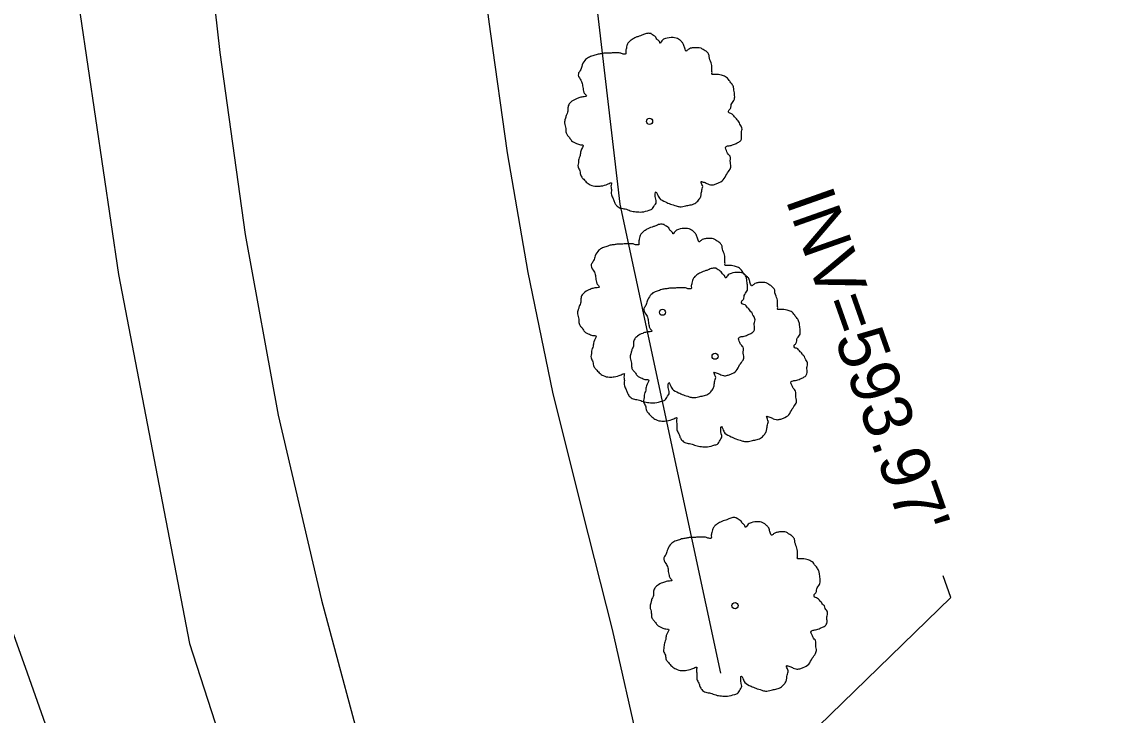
# Model space of a CAD drawing. Extents: x 2004847 to 2009016, y 1134161 to 1140101.
# Drawn here: x 2005249.9 to 2005339.3, y 1139472.4 to 1139529 of the extents above; entities that cross this region are included whole.
import ezdxf

# ---------------------------------------------------------------- set-up
doc = ezdxf.new("R2010")
doc.units = 0
for name, color, linetype in [('RD_EX_DR_Inlet_txCode', 7, 'Continuous'), ('RD_EX_Fence_Other', 7, 'Continuous'), ('RD_EX_H2O', 7, 'Continuous'), ('RD_EX_Road', 7, 'Continuous'), ('RD_EX_VEG', 7, 'Continuous')]:
    doc.layers.add(name, color=color, linetype=linetype)

msp = doc.modelspace()

# ---------------------------------------------------------------- linework, layer by layer
at = {"layer": 'RD_EX_DR_Inlet_txCode'}
msp.add_lwpolyline([(2005310.045, 1139466.714), (2005325.794, 1139482.013), (2005325.165, 1139483.793)], dxfattribs=at)
at = {"layer": 'RD_EX_Fence_Other'}
msp.add_lwpolyline([(2005253.027, 1139716.132), (2005238.254, 1139668.781), (2005212.869, 1139585.207), (2005223.769, 1139551.444), (2005241.149, 1139501.523), (2005250.303, 1139475.866), (2005274.937, 1139406.133)], dxfattribs=at)
at = {"layer": 'RD_EX_H2O'}
msp.add_line((2005298.755, 1139514.148), (2005306.974, 1139475.853), dxfattribs=at)
for points in [[(2005258.132, 1139714.456), (2005253.872, 1139663.93), (2005250.076, 1139582.798), (2005251.507, 1139550.898), (2005257.79, 1139508.395), (2005263.585, 1139478.258), (2005286.366, 1139407.794), (2005304.78, 1139341.828)], [(2005299.739, 1139659.564), (2005292.279, 1139582.182), (2005293.644, 1139557.733), (2005298.755, 1139514.148)]]:
    msp.add_lwpolyline(points, dxfattribs=at)
at = {"layer": 'RD_EX_Road'}
for points in [[(2005262.051, 1139571.916), (2005263.041, 1139556.953), (2005264.31, 1139542.01), (2005266.061, 1139526.537), (2005268.134, 1139511.675), (2005270.817, 1139496.924), (2005274.378, 1139481.81), (2005278.256, 1139467.332), (2005282.356, 1139452.916), (2005286.707, 1139438.571), (2005291.182, 1139424.261), (2005295.677, 1139409.956), (2005300.517, 1139395.441), (2005305.551, 1139381.315), (2005310.576, 1139367.186), (2005315.506, 1139353.023), (2005320.719, 1139338.96), (2005325.801, 1139324.851), (2005330.861, 1139310.729), (2005335.767, 1139296.554), (2005340.823, 1139282.434)], [(2005284.086, 1139567.589), (2005284.726, 1139557.612), (2005285.696, 1139548.131), (2005286.816, 1139538.175), (2005288.153, 1139528.259), (2005289.539, 1139518.351), (2005291.221, 1139508.575), (2005293.244, 1139498.788), (2005295.658, 1139489.087), (2005298.121, 1139479.396), (2005300.33, 1139469.65), (2005303.203, 1139460.049), (2005305.845, 1139450.53), (2005309.03, 1139441.031), (2005312.07, 1139431.495), (2005314.223, 1139425.334), (2005316.148, 1139423.068), (2005322.431, 1139419.852), (2005326.067, 1139418.258), (2005330.045, 1139416.594), (2005332.094, 1139409.223)]]:
    msp.add_lwpolyline(points, dxfattribs=at)
at = {"layer": 'RD_EX_VEG'}
for centre, radius in [((2005301.168, 1139520.915), 0.25), ((2005301.155, 1139520.896), 0.0001), ((2005302.228, 1139505.324), 0.25), ((2005302.215, 1139505.305), 0.0001), ((2005306.525, 1139501.731), 0.25), ((2005306.512, 1139501.713), 0.0001), ((2005308.155, 1139481.359), 0.25), ((2005308.142, 1139481.34), 0.0001)]:
    msp.add_circle(centre, radius, dxfattribs=at)
for points in [[(2005301.299, 1139528.082), (2005301, 1139528.107), (2005300.675, 1139528.007), (2005300.425, 1139527.907), (2005300.2, 1139527.832), (2005299.975, 1139527.732), (2005299.675, 1139527.557), (2005299.45, 1139527.357), (2005299.325, 1139527.108), (2005299.275, 1139526.883), (2005299.225, 1139526.608), (2005299.225, 1139526.433), (2005299.1, 1139526.408), (2005298.95, 1139526.433), (2005298.701, 1139526.508), (2005298.451, 1139526.508), (2005298.201, 1139526.508), (2005297.851, 1139526.483), (2005297.501, 1139526.483), (2005297.226, 1139526.433), (2005296.901, 1139526.383), (2005296.526, 1139526.258), (2005296.177, 1139526.133), (2005295.877, 1139525.883), (2005295.627, 1139525.408), (2005295.502, 1139525.058), (2005295.352, 1139524.809), (2005295.502, 1139524.359), (2005295.677, 1139524.009), (2005295.702, 1139523.809), (2005295.777, 1139523.384), (2005295.877, 1139523.159), (2005296.002, 1139522.959), (2005295.927, 1139522.934), (2005295.552, 1139522.884), (2005295.252, 1139522.784), (2005294.827, 1139522.56), (2005294.602, 1139522.335), (2005294.502, 1139522.01), (2005294.477, 1139521.66), (2005294.377, 1139521.46), (2005294.302, 1139521.185), (2005294.277, 1139521.11), (2005294.227, 1139520.785), (2005294.327, 1139520.335), (2005294.352, 1139519.986), (2005294.477, 1139519.761), (2005294.627, 1139519.586), (2005294.802, 1139519.336), (2005295.202, 1139519.111), (2005295.527, 1139519.011), (2005295.727, 1139518.986), (2005295.552, 1139518.486), (2005295.502, 1139518.136), (2005295.377, 1139517.737), (2005295.377, 1139517.662), (2005295.327, 1139517.187), (2005295.477, 1139516.862), (2005295.552, 1139516.487), (2005295.727, 1139516.262), (2005296.002, 1139515.962), (2005296.327, 1139515.738), (2005296.826, 1139515.613), (2005297.226, 1139515.638), (2005297.801, 1139515.812), (2005298.051, 1139515.887), (2005298.026, 1139515.713), (2005298.051, 1139515.338), (2005298.051, 1139514.913), (2005298.201, 1139514.588), (2005298.301, 1139514.313), (2005298.451, 1139514.063), (2005298.776, 1139513.838), (2005299.175, 1139513.763), (2005299.6, 1139513.613), (2005300.05, 1139513.538), (2005300.55, 1139513.513), (2005301.149, 1139513.663), (2005301.424, 1139513.788), (2005301.524, 1139513.963), (2005301.724, 1139514.338), (2005301.674, 1139514.563), (2005301.699, 1139515.163), (2005301.799, 1139514.988), (2005301.974, 1139514.638), (2005302.474, 1139514.338), (2005302.874, 1139514.163), (2005303.348, 1139514.013), (2005303.648, 1139513.938), (2005304.123, 1139514.013), (2005304.498, 1139514.088), (2005304.873, 1139514.213), (2005305.173, 1139514.488), (2005305.348, 1139514.763), (2005305.398, 1139515.038), (2005305.473, 1139515.413), (2005305.523, 1139515.588)], [(2005305.523, 1139515.588), (2005305.448, 1139515.763), (2005305.398, 1139516.012), (2005305.473, 1139515.987), (2005305.647, 1139515.937), (2005305.922, 1139515.812), (2005306.147, 1139515.738), (2005306.472, 1139515.763), (2005306.747, 1139515.862), (2005307.197, 1139516.137), (2005307.472, 1139516.612), (2005307.747, 1139517.012), (2005307.822, 1139517.337), (2005307.772, 1139517.562), (2005307.747, 1139518.061), (2005307.547, 1139518.311), (2005307.497, 1139518.436), (2005307.397, 1139518.836), (2005307.472, 1139518.886), (2005307.747, 1139518.936), (2005308.121, 1139519.061), (2005308.396, 1139519.186), (2005308.621, 1139519.361), (2005308.696, 1139519.586), (2005308.671, 1139519.986), (2005308.721, 1139520.385), (2005308.646, 1139520.535), (2005308.546, 1139520.685), (2005308.471, 1139520.885), (2005308.321, 1139521.035), (2005308.221, 1139521.185), (2005308.121, 1139521.285), (2005307.996, 1139521.435), (2005307.822, 1139521.56), (2005307.672, 1139521.61), (2005307.622, 1139521.76), (2005307.772, 1139521.96), (2005307.822, 1139522.06), (2005307.846, 1139522.285), (2005308.071, 1139522.634), (2005308.121, 1139523.034), (2005308.071, 1139523.459), (2005308.021, 1139523.734), (2005307.871, 1139524.009), (2005307.672, 1139524.259), (2005307.547, 1139524.434), (2005307.372, 1139524.559), (2005307.047, 1139524.684), (2005306.797, 1139524.734), (2005306.447, 1139524.734), (2005306.247, 1139524.784), (2005306.272, 1139524.834), (2005306.272, 1139524.983), (2005306.272, 1139525.258), (2005306.197, 1139525.708), (2005306.047, 1139526.208), (2005306.047, 1139526.233), (2005305.947, 1139526.483), (2005305.722, 1139526.683), (2005305.548, 1139526.783), (2005305.348, 1139526.908), (2005305.098, 1139526.933), (2005304.798, 1139526.933), (2005304.523, 1139526.883), (2005304.323, 1139526.783), (2005304.148, 1139526.658), (2005304.073, 1139526.808), (2005303.973, 1139527.108), (2005303.923, 1139527.257), (2005303.773, 1139527.432), (2005303.548, 1139527.632), (2005303.099, 1139527.757), (2005302.474, 1139527.682), (2005302.174, 1139527.482), (2005302.024, 1139527.307), (2005301.974, 1139527.432), (2005301.774, 1139527.632), (2005301.674, 1139527.807), (2005301.499, 1139527.932), (2005301.349, 1139528.032), (2005301.249, 1139528.082)], [(2005302.36, 1139512.491), (2005302.06, 1139512.516), (2005301.735, 1139512.416), (2005301.485, 1139512.317), (2005301.26, 1139512.242), (2005301.035, 1139512.142), (2005300.735, 1139511.967), (2005300.51, 1139511.767), (2005300.385, 1139511.517), (2005300.335, 1139511.292), (2005300.285, 1139511.017), (2005300.285, 1139510.842), (2005300.161, 1139510.817), (2005300.011, 1139510.842), (2005299.761, 1139510.917), (2005299.511, 1139510.917), (2005299.261, 1139510.917), (2005298.911, 1139510.892), (2005298.561, 1139510.892), (2005298.286, 1139510.842), (2005297.961, 1139510.792), (2005297.587, 1139510.667), (2005297.237, 1139510.542), (2005296.937, 1139510.292), (2005296.687, 1139509.818), (2005296.562, 1139509.468), (2005296.412, 1139509.218), (2005296.562, 1139508.768), (2005296.737, 1139508.418), (2005296.762, 1139508.218), (2005296.837, 1139507.794), (2005296.937, 1139507.569), (2005297.062, 1139507.369), (2005296.987, 1139507.344), (2005296.612, 1139507.294), (2005296.312, 1139507.194), (2005295.887, 1139506.969), (2005295.662, 1139506.744), (2005295.562, 1139506.419), (2005295.538, 1139506.069), (2005295.438, 1139505.869), (2005295.363, 1139505.594), (2005295.338, 1139505.519), (2005295.288, 1139505.195), (2005295.388, 1139504.745), (2005295.413, 1139504.395), (2005295.538, 1139504.17), (2005295.687, 1139503.995), (2005295.862, 1139503.745), (2005296.262, 1139503.52), (2005296.587, 1139503.42), (2005296.787, 1139503.395), (2005296.612, 1139502.896), (2005296.562, 1139502.546), (2005296.437, 1139502.146), (2005296.437, 1139502.071), (2005296.387, 1139501.596), (2005296.537, 1139501.271), (2005296.612, 1139500.897), (2005296.787, 1139500.672), (2005297.062, 1139500.372), (2005297.387, 1139500.147), (2005297.887, 1139500.022), (2005298.286, 1139500.047), (2005298.861, 1139500.222), (2005299.111, 1139500.297), (2005299.086, 1139500.122), (2005299.111, 1139499.747), (2005299.111, 1139499.322), (2005299.261, 1139498.997), (2005299.361, 1139498.722), (2005299.511, 1139498.473), (2005299.836, 1139498.248), (2005300.235, 1139498.173), (2005300.66, 1139498.023), (2005301.11, 1139497.948), (2005301.61, 1139497.923), (2005302.21, 1139498.073), (2005302.484, 1139498.198), (2005302.584, 1139498.373), (2005302.784, 1139498.747), (2005302.734, 1139498.972), (2005302.759, 1139499.572), (2005302.859, 1139499.397), (2005303.034, 1139499.047), (2005303.534, 1139498.747), (2005303.934, 1139498.573), (2005304.409, 1139498.423), (2005304.709, 1139498.348), (2005305.183, 1139498.423), (2005305.558, 1139498.498), (2005305.933, 1139498.623), (2005306.233, 1139498.897), (2005306.408, 1139499.172), (2005306.458, 1139499.447), (2005306.533, 1139499.822), (2005306.583, 1139499.997)], [(2005306.583, 1139499.997), (2005306.508, 1139500.172), (2005306.458, 1139500.422), (2005306.533, 1139500.397), (2005306.708, 1139500.347), (2005306.983, 1139500.222), (2005307.207, 1139500.147), (2005307.532, 1139500.172), (2005307.807, 1139500.272), (2005308.257, 1139500.547), (2005308.532, 1139501.021), (2005308.807, 1139501.421), (2005308.882, 1139501.746), (2005308.832, 1139501.971), (2005308.807, 1139502.471), (2005308.607, 1139502.721), (2005308.557, 1139502.846), (2005308.457, 1139503.245), (2005308.532, 1139503.295), (2005308.807, 1139503.345), (2005309.182, 1139503.47), (2005309.456, 1139503.595), (2005309.681, 1139503.77), (2005309.756, 1139503.995), (2005309.731, 1139504.395), (2005309.781, 1139504.795), (2005309.706, 1139504.945), (2005309.606, 1139505.095), (2005309.531, 1139505.295), (2005309.381, 1139505.444), (2005309.282, 1139505.594), (2005309.182, 1139505.694), (2005309.057, 1139505.844), (2005308.882, 1139505.969), (2005308.732, 1139506.019), (2005308.682, 1139506.169), (2005308.832, 1139506.369), (2005308.882, 1139506.469), (2005308.907, 1139506.694), (2005309.132, 1139507.044), (2005309.182, 1139507.444), (2005309.132, 1139507.868), (2005309.082, 1139508.143), (2005308.932, 1139508.418), (2005308.732, 1139508.668), (2005308.607, 1139508.843), (2005308.432, 1139508.968), (2005308.107, 1139509.093), (2005307.857, 1139509.143), (2005307.507, 1139509.143), (2005307.307, 1139509.193), (2005307.332, 1139509.243), (2005307.332, 1139509.393), (2005307.332, 1139509.668), (2005307.257, 1139510.117), (2005307.107, 1139510.617), (2005307.107, 1139510.642), (2005307.007, 1139510.892), (2005306.783, 1139511.092), (2005306.608, 1139511.192), (2005306.408, 1139511.317), (2005306.158, 1139511.342), (2005305.858, 1139511.342), (2005305.583, 1139511.292), (2005305.383, 1139511.192), (2005305.208, 1139511.067), (2005305.133, 1139511.217), (2005305.033, 1139511.517), (2005304.983, 1139511.667), (2005304.833, 1139511.842), (2005304.609, 1139512.042), (2005304.159, 1139512.167), (2005303.534, 1139512.092), (2005303.234, 1139511.892), (2005303.084, 1139511.717), (2005303.034, 1139511.842), (2005302.834, 1139512.042), (2005302.734, 1139512.217), (2005302.559, 1139512.342), (2005302.41, 1139512.441), (2005302.31, 1139512.491)], [(2005306.657, 1139508.899), (2005306.357, 1139508.924), (2005306.032, 1139508.824), (2005305.782, 1139508.724), (2005305.557, 1139508.649), (2005305.332, 1139508.549), (2005305.032, 1139508.374), (2005304.808, 1139508.174), (2005304.683, 1139507.924), (2005304.633, 1139507.699), (2005304.583, 1139507.424), (2005304.583, 1139507.249), (2005304.458, 1139507.224), (2005304.308, 1139507.249), (2005304.058, 1139507.324), (2005303.808, 1139507.324), (2005303.558, 1139507.324), (2005303.208, 1139507.299), (2005302.858, 1139507.299), (2005302.584, 1139507.249), (2005302.259, 1139507.199), (2005301.884, 1139507.074), (2005301.534, 1139506.949), (2005301.234, 1139506.7), (2005300.984, 1139506.225), (2005300.859, 1139505.875), (2005300.709, 1139505.625), (2005300.859, 1139505.175), (2005301.034, 1139504.825), (2005301.059, 1139504.625), (2005301.134, 1139504.201), (2005301.234, 1139503.976), (2005301.359, 1139503.776), (2005301.284, 1139503.751), (2005300.909, 1139503.701), (2005300.609, 1139503.601), (2005300.185, 1139503.376), (2005299.96, 1139503.151), (2005299.86, 1139502.826), (2005299.835, 1139502.476), (2005299.735, 1139502.277), (2005299.66, 1139502.002), (2005299.635, 1139501.927), (2005299.585, 1139501.602), (2005299.685, 1139501.152), (2005299.71, 1139500.802), (2005299.835, 1139500.577), (2005299.985, 1139500.402), (2005300.16, 1139500.152), (2005300.559, 1139499.928), (2005300.884, 1139499.828), (2005301.084, 1139499.803), (2005300.909, 1139499.303), (2005300.859, 1139498.953), (2005300.734, 1139498.553), (2005300.734, 1139498.478), (2005300.684, 1139498.003), (2005300.834, 1139497.678), (2005300.909, 1139497.304), (2005301.084, 1139497.079), (2005301.359, 1139496.779), (2005301.684, 1139496.554), (2005302.184, 1139496.429), (2005302.584, 1139496.454), (2005303.158, 1139496.629), (2005303.408, 1139496.704), (2005303.383, 1139496.529), (2005303.408, 1139496.154), (2005303.408, 1139495.729), (2005303.558, 1139495.405), (2005303.658, 1139495.13), (2005303.808, 1139494.88), (2005304.133, 1139494.655), (2005304.533, 1139494.58), (2005304.957, 1139494.43), (2005305.407, 1139494.355), (2005305.907, 1139494.33), (2005306.507, 1139494.48), (2005306.782, 1139494.605), (2005306.882, 1139494.78), (2005307.082, 1139495.155), (2005307.032, 1139495.38), (2005307.057, 1139495.979), (2005307.156, 1139495.804), (2005307.331, 1139495.454), (2005307.831, 1139495.155), (2005308.231, 1139494.98), (2005308.706, 1139494.83), (2005309.006, 1139494.755), (2005309.48, 1139494.83), (2005309.855, 1139494.905), (2005310.23, 1139495.03), (2005310.53, 1139495.305), (2005310.705, 1139495.579), (2005310.755, 1139495.854), (2005310.83, 1139496.229), (2005310.88, 1139496.404)], [(2005310.88, 1139496.404), (2005310.805, 1139496.579), (2005310.755, 1139496.829), (2005310.83, 1139496.804), (2005311.005, 1139496.754), (2005311.28, 1139496.629), (2005311.505, 1139496.554), (2005311.829, 1139496.579), (2005312.104, 1139496.679), (2005312.554, 1139496.954), (2005312.829, 1139497.429), (2005313.104, 1139497.828), (2005313.179, 1139498.153), (2005313.129, 1139498.378), (2005313.104, 1139498.878), (2005312.904, 1139499.128), (2005312.854, 1139499.253), (2005312.754, 1139499.653), (2005312.829, 1139499.703), (2005313.104, 1139499.753), (2005313.479, 1139499.878), (2005313.754, 1139500.002), (2005313.979, 1139500.177), (2005314.053, 1139500.402), (2005314.029, 1139500.802), (2005314.078, 1139501.202), (2005314.004, 1139501.352), (2005313.904, 1139501.502), (2005313.829, 1139501.702), (2005313.679, 1139501.852), (2005313.579, 1139502.002), (2005313.479, 1139502.102), (2005313.354, 1139502.252), (2005313.179, 1139502.376), (2005313.029, 1139502.426), (2005312.979, 1139502.576), (2005313.129, 1139502.776), (2005313.179, 1139502.876), (2005313.204, 1139503.101), (2005313.429, 1139503.451), (2005313.479, 1139503.851), (2005313.429, 1139504.276), (2005313.379, 1139504.551), (2005313.229, 1139504.825), (2005313.029, 1139505.075), (2005312.904, 1139505.25), (2005312.729, 1139505.375), (2005312.404, 1139505.5), (2005312.154, 1139505.55), (2005311.804, 1139505.55), (2005311.605, 1139505.6), (2005311.63, 1139505.65), (2005311.63, 1139505.8), (2005311.63, 1139506.075), (2005311.555, 1139506.525), (2005311.405, 1139507.024), (2005311.405, 1139507.049), (2005311.305, 1139507.299), (2005311.08, 1139507.499), (2005310.905, 1139507.599), (2005310.705, 1139507.724), (2005310.455, 1139507.749), (2005310.155, 1139507.749), (2005309.88, 1139507.699), (2005309.68, 1139507.599), (2005309.505, 1139507.474), (2005309.43, 1139507.624), (2005309.331, 1139507.924), (2005309.281, 1139508.074), (2005309.131, 1139508.249), (2005308.906, 1139508.449), (2005308.456, 1139508.574), (2005307.831, 1139508.499), (2005307.531, 1139508.299), (2005307.381, 1139508.124), (2005307.331, 1139508.249), (2005307.131, 1139508.449), (2005307.032, 1139508.624), (2005306.857, 1139508.749), (2005306.707, 1139508.849), (2005306.607, 1139508.899)], [(2005308.287, 1139488.527), (2005307.987, 1139488.552), (2005307.662, 1139488.452), (2005307.412, 1139488.352), (2005307.187, 1139488.277), (2005306.962, 1139488.177), (2005306.662, 1139488.002), (2005306.437, 1139487.802), (2005306.312, 1139487.552), (2005306.262, 1139487.327), (2005306.212, 1139487.052), (2005306.212, 1139486.877), (2005306.088, 1139486.852), (2005305.938, 1139486.877), (2005305.688, 1139486.952), (2005305.438, 1139486.952), (2005305.188, 1139486.952), (2005304.838, 1139486.927), (2005304.488, 1139486.927), (2005304.213, 1139486.877), (2005303.888, 1139486.827), (2005303.514, 1139486.702), (2005303.164, 1139486.577), (2005302.864, 1139486.327), (2005302.614, 1139485.853), (2005302.489, 1139485.503), (2005302.339, 1139485.253), (2005302.489, 1139484.803), (2005302.664, 1139484.453), (2005302.689, 1139484.253), (2005302.764, 1139483.829), (2005302.864, 1139483.604), (2005302.989, 1139483.404), (2005302.914, 1139483.379), (2005302.539, 1139483.329), (2005302.239, 1139483.229), (2005301.814, 1139483.004), (2005301.589, 1139482.779), (2005301.489, 1139482.454), (2005301.465, 1139482.104), (2005301.365, 1139481.904), (2005301.29, 1139481.63), (2005301.265, 1139481.555), (2005301.215, 1139481.23), (2005301.315, 1139480.78), (2005301.34, 1139480.43), (2005301.465, 1139480.205), (2005301.614, 1139480.03), (2005301.789, 1139479.78), (2005302.189, 1139479.555), (2005302.514, 1139479.455), (2005302.714, 1139479.431), (2005302.539, 1139478.931), (2005302.489, 1139478.581), (2005302.364, 1139478.181), (2005302.364, 1139478.106), (2005302.314, 1139477.631), (2005302.464, 1139477.306), (2005302.539, 1139476.932), (2005302.714, 1139476.707), (2005302.989, 1139476.407), (2005303.314, 1139476.182), (2005303.814, 1139476.057), (2005304.213, 1139476.082), (2005304.788, 1139476.257), (2005305.038, 1139476.332), (2005305.013, 1139476.157), (2005305.038, 1139475.782), (2005305.038, 1139475.357), (2005305.188, 1139475.032), (2005305.288, 1139474.758), (2005305.438, 1139474.508), (2005305.763, 1139474.283), (2005306.162, 1139474.208), (2005306.587, 1139474.058), (2005307.037, 1139473.983), (2005307.537, 1139473.958), (2005308.137, 1139474.108), (2005308.411, 1139474.233), (2005308.511, 1139474.408), (2005308.711, 1139474.783), (2005308.661, 1139475.007), (2005308.686, 1139475.607), (2005308.786, 1139475.432), (2005308.961, 1139475.082), (2005309.461, 1139474.783), (2005309.861, 1139474.608), (2005310.336, 1139474.458), (2005310.636, 1139474.383), (2005311.11, 1139474.458), (2005311.485, 1139474.533), (2005311.86, 1139474.658), (2005312.16, 1139474.932), (2005312.335, 1139475.207), (2005312.385, 1139475.482), (2005312.46, 1139475.857), (2005312.51, 1139476.032)], [(2005312.51, 1139476.032), (2005312.435, 1139476.207), (2005312.385, 1139476.457), (2005312.46, 1139476.432), (2005312.635, 1139476.382), (2005312.91, 1139476.257), (2005313.134, 1139476.182), (2005313.459, 1139476.207), (2005313.734, 1139476.307), (2005314.184, 1139476.582), (2005314.459, 1139477.057), (2005314.734, 1139477.456), (2005314.809, 1139477.781), (2005314.759, 1139478.006), (2005314.734, 1139478.506), (2005314.534, 1139478.756), (2005314.484, 1139478.881), (2005314.384, 1139479.281), (2005314.459, 1139479.331), (2005314.734, 1139479.381), (2005315.109, 1139479.505), (2005315.383, 1139479.63), (2005315.608, 1139479.805), (2005315.683, 1139480.03), (2005315.658, 1139480.43), (2005315.708, 1139480.83), (2005315.633, 1139480.98), (2005315.533, 1139481.13), (2005315.458, 1139481.33), (2005315.308, 1139481.48), (2005315.209, 1139481.63), (2005315.109, 1139481.729), (2005314.984, 1139481.879), (2005314.809, 1139482.004), (2005314.659, 1139482.054), (2005314.609, 1139482.204), (2005314.759, 1139482.404), (2005314.809, 1139482.504), (2005314.834, 1139482.729), (2005315.059, 1139483.079), (2005315.109, 1139483.479), (2005315.059, 1139483.904), (2005315.009, 1139484.178), (2005314.859, 1139484.453), (2005314.659, 1139484.703), (2005314.534, 1139484.878), (2005314.359, 1139485.003), (2005314.034, 1139485.128), (2005313.784, 1139485.178), (2005313.434, 1139485.178), (2005313.234, 1139485.228), (2005313.259, 1139485.278), (2005313.259, 1139485.428), (2005313.259, 1139485.703), (2005313.184, 1139486.153), (2005313.034, 1139486.652), (2005313.034, 1139486.677), (2005312.934, 1139486.927), (2005312.71, 1139487.127), (2005312.535, 1139487.227), (2005312.335, 1139487.352), (2005312.085, 1139487.377), (2005311.785, 1139487.377), (2005311.51, 1139487.327), (2005311.31, 1139487.227), (2005311.135, 1139487.102), (2005311.06, 1139487.252), (2005310.96, 1139487.552), (2005310.91, 1139487.702), (2005310.76, 1139487.877), (2005310.536, 1139488.077), (2005310.086, 1139488.202), (2005309.461, 1139488.127), (2005309.161, 1139487.927), (2005309.011, 1139487.752), (2005308.961, 1139487.877), (2005308.761, 1139488.077), (2005308.661, 1139488.252), (2005308.486, 1139488.377), (2005308.337, 1139488.477), (2005308.237, 1139488.527)]]:
    msp.add_spline(points, degree=3, dxfattribs=at)

# ---------------------------------------------------------------- texts
at = {"layer": 'RD_EX_DR_Inlet_txCode'}
msp.add_text("INV=593.97'", height=4.00001, rotation=289.44941, dxfattribs=at).set_placement((2005312.251, 1139514.553))

doc.saveas('drawing.dxf')
